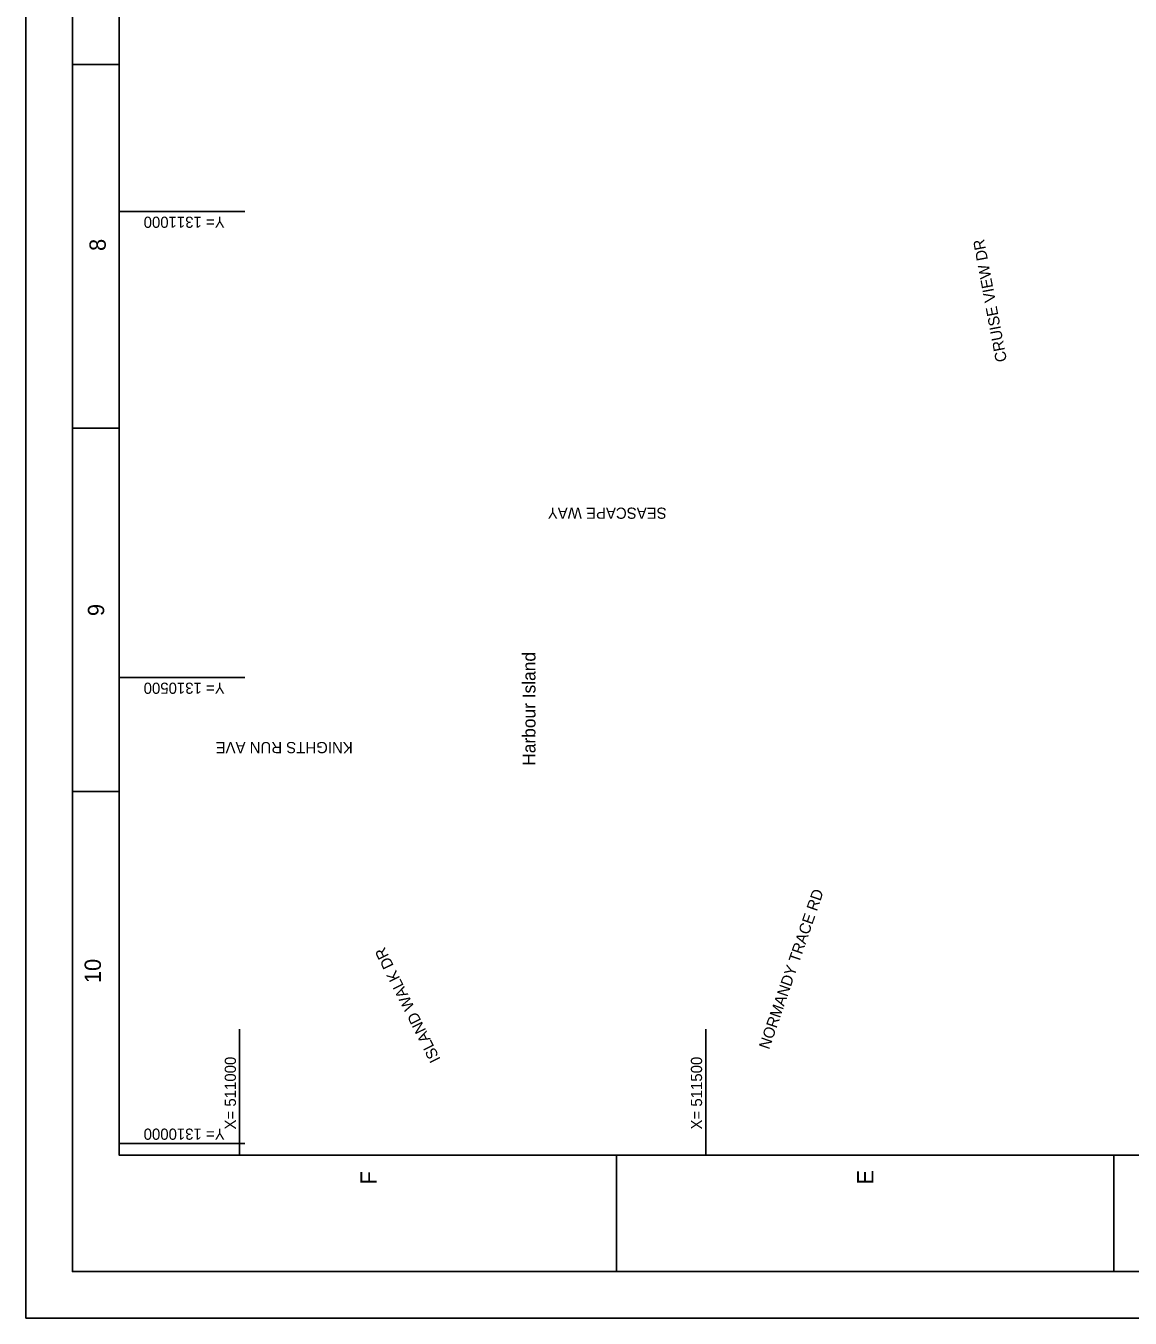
# Model space of a CAD drawing. Extents: x 510771 to 514171, y 1309813 to 1314213.
# Drawn here: x 510771 to 511955, y 1309813 to 1311199 of the extents above; entities that cross this region are included whole.
import ezdxf

# ---------------------------------------------------------------- set-up
doc = ezdxf.new("R2010")
doc.units = 0
for name, color, linetype in [('G-ANNO-NPLT', 7, 'Continuous'), ('G-ANNO-TTLB', 7, 'Continuous'), ('V-ROAD-IDEN', 7, 'Continuous'), ('V-SITE-IDEN', 7, 'Continuous'), ('V-TOPO-COOR-STAT', 7, 'Continuous')]:
    doc.layers.add(name, color=color, linetype=linetype)

msp = doc.modelspace()

# ---------------------------------------------------------------- linework, layer by layer
at = {"layer": 'G-ANNO-NPLT'}
msp.add_lwpolyline([(510770.7, 1309812.6), (510770.7, 1314212.6), (514170.7, 1314212.6), (514170.7, 1309812.6)], close=True, dxfattribs=at)
msp.add_lwpolyline([(510820.7, 1309812.6), (510770.7, 1309812.6), (510770.7, 1309862.6)], dxfattribs=at)
at = {"layer": 'G-ANNO-TTLB'}
for p, q in [((510820.7, 1311157.6), (510870.7, 1311157.6)), ((510820.7, 1310767.6), (510870.7, 1310767.6)), ((510820.7, 1310767.6), (510870.7, 1310767.6)), ((510820.7, 1310377.6), (510870.7, 1310377.6)), ((511404.2, 1309862.6), (511404.2, 1309987.6)), ((511937.5, 1309862.6), (511937.5, 1309987.6))]:
    msp.add_line(p, q, dxfattribs=at)
for points in [[(514120.7, 1309862.6), (514120.7, 1314162.6), (510820.7, 1314162.6), (510820.7, 1309862.6)], [(510870.7, 1314112.6), (510870.7, 1309987.6), (514070.7, 1309987.6), (514070.7, 1314112.6)]]:
    msp.add_lwpolyline(points, close=True, dxfattribs=at)
at = {"layer": 'V-TOPO-COOR-STAT'}
for p, q in [((511005.7, 1311000), (510870.7, 1311000)), ((511005.7, 1310500), (510870.7, 1310500)), ((511000, 1309987.6), (511000, 1310122.6)), ((511500, 1309987.6), (511500, 1310122.6)), ((511005.7, 1310000), (510870.7, 1310000))]:
    msp.add_line(p, q, dxfattribs=at)

# ---------------------------------------------------------------- texts
at = {"layer": 'G-ANNO-TTLB'}
for s, p in [('8', (510856.4, 1310957.7)), ('9', (510854.7, 1310565.9)), ('10', (510851.2, 1310172.1)), ('F', (511147, 1309956.1)), ('E', (511679.7, 1309956))]:
    msp.add_text(s, height=17.5, rotation=90, dxfattribs=at).set_placement(p)
at = {"layer": 'V-ROAD-IDEN'}
for s, rotation, p in [('CRUISE VIEW DR', 100.6731, (511823.1, 1310839.7)), ('SEASCAPE WAY', 180, (511458, 1310682.3)), ('KNIGHTS RUN AVE', 180, (511121.3, 1310430.8)), ('NORMANDY TRACE RD', 70.9746, (511567.9, 1310100.2)), ('ISLAND WALK DR', 116.4892, (511215.7, 1310090.3))]:
    msp.add_text(s, height=12, rotation=rotation, dxfattribs=at).set_placement(p)
at = {"layer": 'V-SITE-IDEN'}
msp.add_text('Harbour Island', height=13.92, rotation=90, dxfattribs=at).set_placement((511317.3, 1310405.3))
at = {"layer": 'V-TOPO-COOR-STAT'}
for s, rotation, p in [('Y= 1311000', 180, (510984, 1310994.5)), ('Y= 1310500', 180, (510984, 1310494.5)), ('X= 511000', 90, (510996, 1310015)), ('X= 511500', 90, (511496, 1310015)), ('Y= 1310000', 180, (510984, 1310016))]:
    msp.add_text(s, height=12, rotation=rotation, dxfattribs=at).set_placement(p)

doc.saveas('drawing.dxf')
